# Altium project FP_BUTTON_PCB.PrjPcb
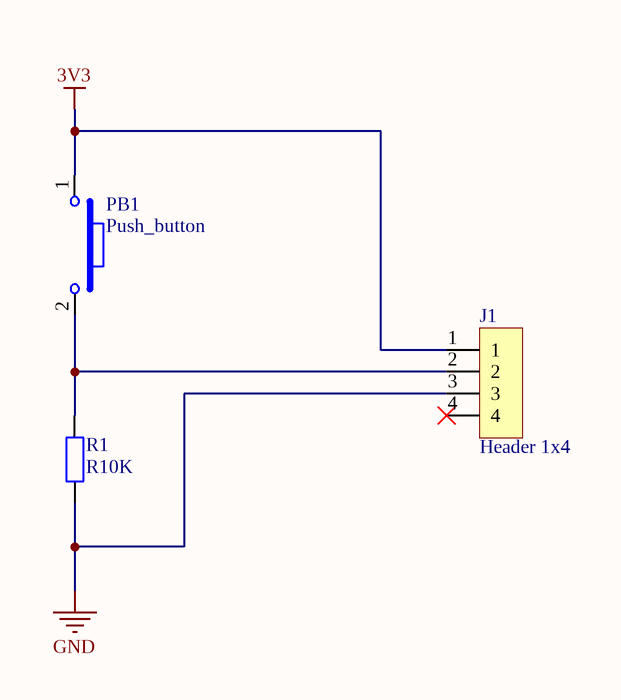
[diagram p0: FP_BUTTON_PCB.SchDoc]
1 sheet, 3 parts. Net scope: global (net labels, ports and power ports of the same name join across sheets).
Board file: FP_BUTTON_PCB.PcbDoc

## Sheet FP_BUTTON_PCB.SchDoc
size A4; SheetNumber: 1; SheetTotal: 1

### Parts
J1  Header 1x4  [HDR4X1_FEMALE]
PB1  Push_button  [button_12x12]
R1  R10K  [RES1206]

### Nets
3V3: J1.1 PB1.1
GND: J1.3 R1.1
NetJ1_2: J1.2 PB1.2 R1.2

Not connected (* = marked no-connect by the designer): J1 4*

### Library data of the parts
PB1 = Push_button: PTS636SM25FSMTR LFS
